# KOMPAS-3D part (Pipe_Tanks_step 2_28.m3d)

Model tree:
1. X Axis
2. Y Axis
3. Z Axis  (labels: Pipe Dn 50)
     Òîëùèíà ñòåíêè 1 = 1

Referenced files in C:\Documents and Settings\kashirsky\Мои документы\Camtasia Studio\Pipelines3D\Tanks\: Tanks_step 2.a3d
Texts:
  Pipe Dn 50
  Steel ASTM A295
  Three Point Plane
  Plane at Angle
  Line and Point Plane
  Axis through Two Vertices
  Axis of Feature
  Axis of Conical Surface
  Axis through Edge
  Trim by Surface
  Trim by Sketch
  Feature with No History
  Intersection Axis of Two Planes
  Two Line Plane
  Line and Face Plane
  Bend by line
  Hole in sheet body
  Cut in sheet body
  Point in CM
  Linear Dimension from Line to Point
  Surface Finish Symbol
  Geometric Tolerance Symbol
  Leader #1
  Leader #2
  Leader #3
  Shape Deviations and Datum
  Node point number
  Mark of coordination axis
  Node point designation
  Mark/Reference designation with leader
  Mark/reference designation on line
  Mark/Reference designation without leader
  Plane of section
